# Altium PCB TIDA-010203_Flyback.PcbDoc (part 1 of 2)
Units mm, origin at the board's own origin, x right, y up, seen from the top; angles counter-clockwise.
Board outline 58 x 45 mm, 2 copper layers (Top Layer, Bottom Layer), stack 1.646 mm thick; 65 components, 31 nets, 152 pads, 52 vias.
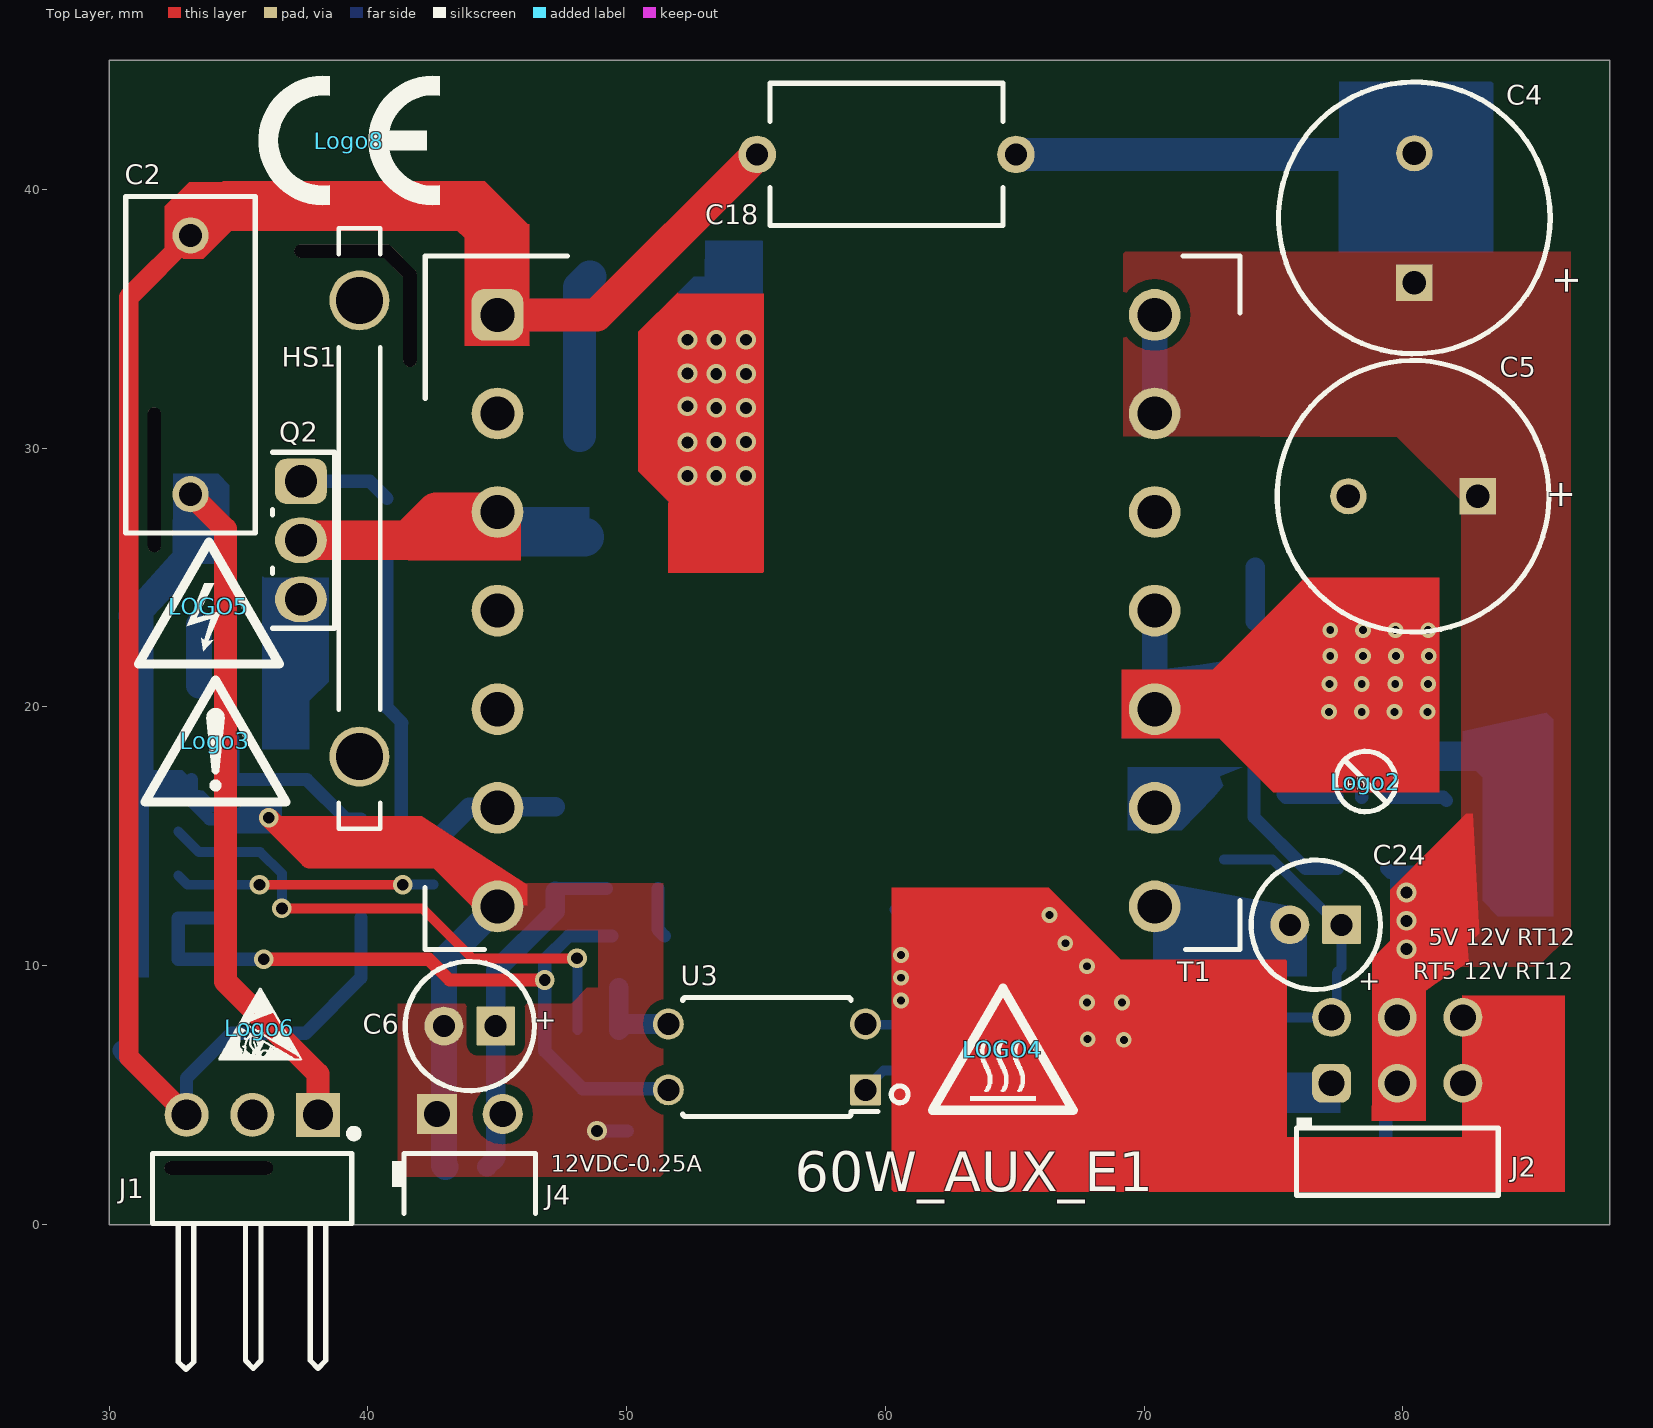
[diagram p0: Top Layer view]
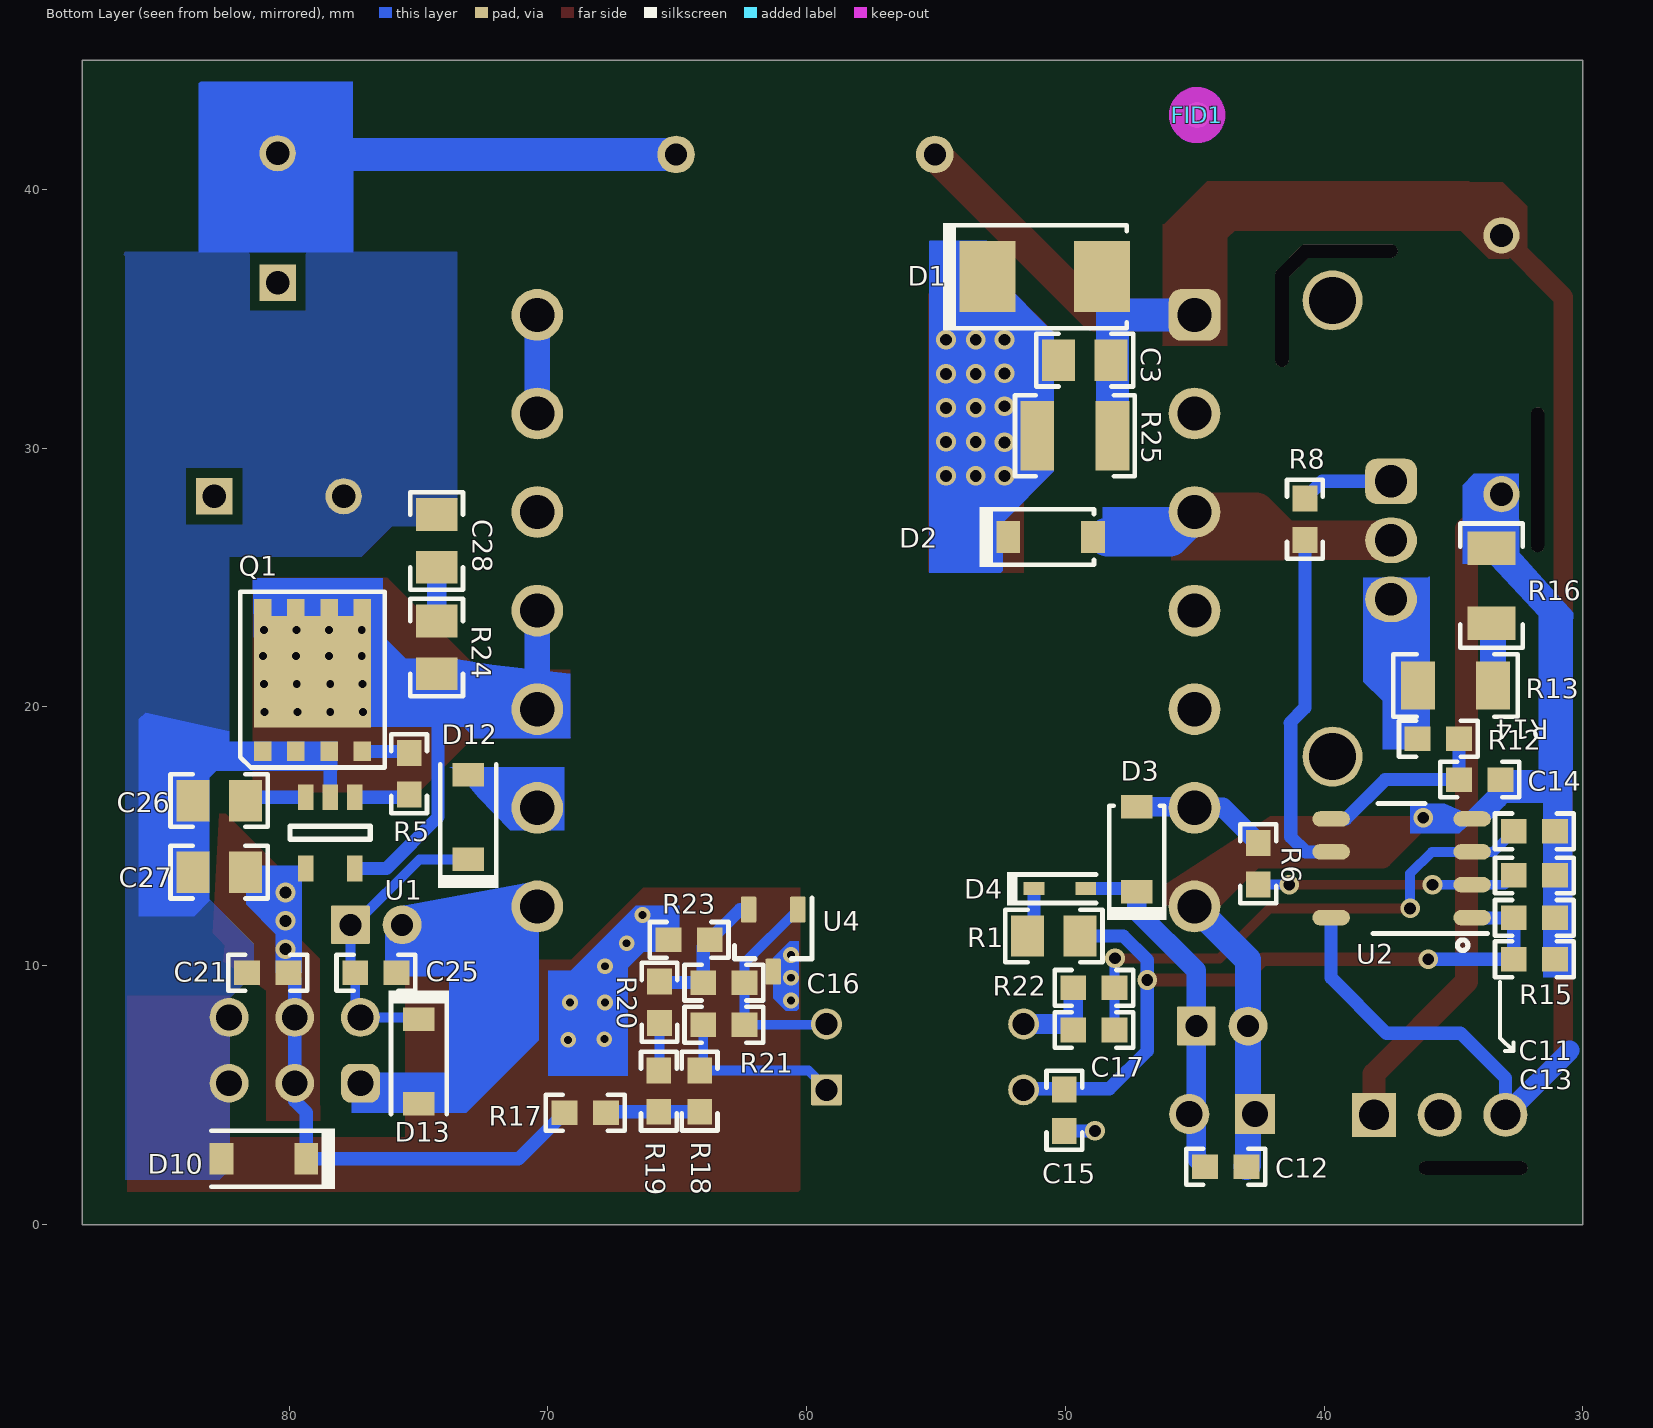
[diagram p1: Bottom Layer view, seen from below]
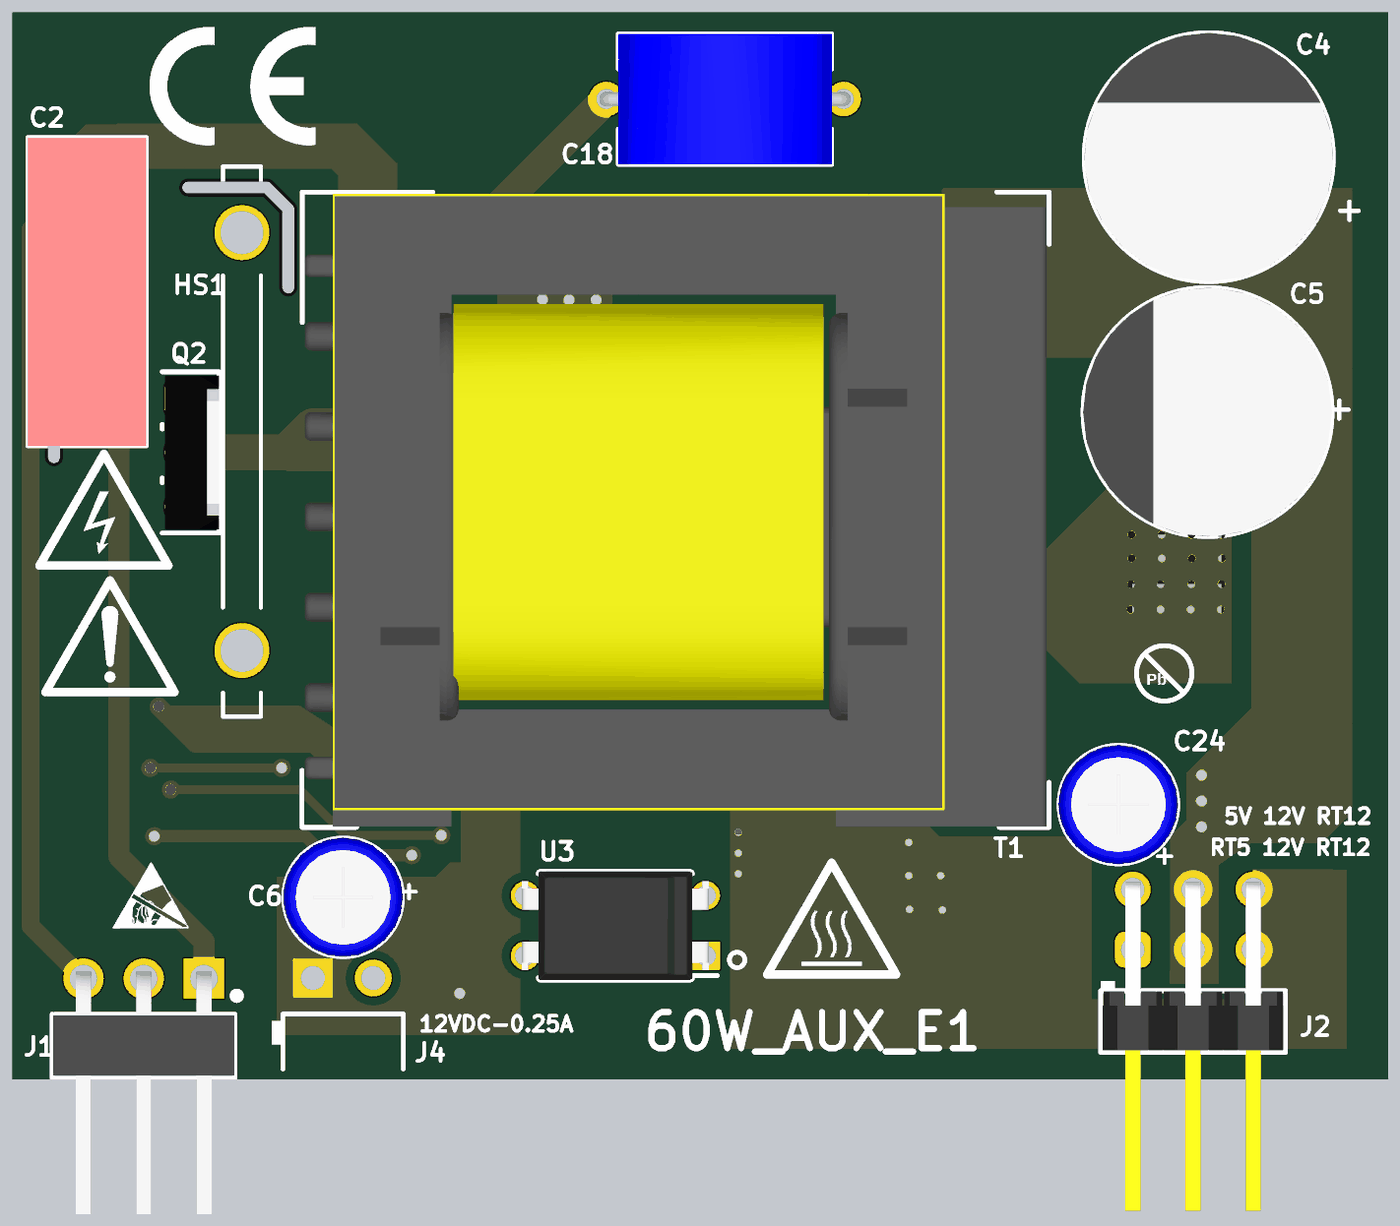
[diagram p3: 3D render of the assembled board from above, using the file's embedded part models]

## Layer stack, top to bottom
Top Solder: solder mask 0.0102, Solder Resist, Dk 3.5
Top Layer: signal copper 0.0711
Dielectric1: core 1.5037, FR-4 High Tg, Dk 4.8
Bottom Layer: signal copper 0.0711
Bottom Solder: solder mask 0.0102, Solder Resist, Dk 3.5

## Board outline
30,0 88,0 88,45 30,45

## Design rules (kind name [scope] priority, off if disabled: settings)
AcuteAngle [All] p1: minimum=4.50000000000000E+0001 checktracksonly=FALSE
AssemblyTestPointUsage [All] p1: valid=2
Clearance Clearance_1 [IsPad vs IsVia] p1: gap=0.203 ignorepadtopadclearanceinfootprint=FALSE except(0: Arc-Hole Track-Hole SMDPad-Hole THPad-Hole Via-Hole Fill-Hole Poly-Hole Region-Hole Text-Hole)
Clearance Clearance_Keepouts [iskeepout vs inpoly] p2: gap=0.508 ignorepadtopadclearanceinfootprint=FALSE except(0: Arc-Hole Track-Hole SMDPad-Hole THPad-Hole Via-Hole Fill-Hole Poly-Hole Region-Hole Text-Hole)
Clearance Clearance_BoardEdge_Poly [OnCopper and InPoly vs IsKeepOut] p3: gap=0.381 ignorepadtopadclearanceinfootprint=FALSE except(0: Arc-Hole Track-Hole SMDPad-Hole THPad-Hole Via-Hole Fill-Hole Poly-Hole Region-Hole Text-Hole)
Clearance Clearance_Poly [InPolygon] p4: gap=0.381 ignorepadtopadclearanceinfootprint=FALSE except(0: Arc-Hole Track-Hole SMDPad-Hole THPad-Hole Via-Hole Fill-Hole Poly-Hole Region-Hole Text-Hole; 0.508: Poly-Poly)
Clearance [All] p5: gap=0.203 ignorepadtopadclearanceinfootprint=FALSE except(0: Arc-Hole Track-Hole SMDPad-Hole THPad-Hole Via-Hole Fill-Hole Poly-Hole Region-Hole Text-Hole)
ComponentClearance [All] p1: gap=0 collisioncheckmode=3 verticalgap=0 showdistances=FALSE
DiffPairsRouting [All] p1: maxlimit=2.54 minlimit=0.254 mostfreqgap=0.254 toplayer_minwidth=0.381 toplayer_maxwidth=0.381 toplayer_prefwidth=0.381 bottomlayer_minwidth=0.381 bottomlayer_maxwidth=0.381 bottomlayer_prefwidth=0.381 maxuncoupledlength=25.4
FabricationTestPointUsage TestPointUsage [All] p1: valid=2 allowmultiple=FALSE
FabricationTestpoint Testpoint [All] p1: side=3 testpointundercomponent=TRUE minsize=1.016 maxsize=2.54 preferedsize=1.524 minholesize=0 maxholesize=1.016 preferedholesize=0.813 testpointgrid=0.025 allowsidetop=TRUE allowsidebottom=TRUE usegrid=TRUE gridtolerance=0
FanoutControl Fanout_LCC [IsLCC] p1: bgadir=Out bgaviamode=Centered fanoutstyle=Auto fanoutdirection=Alternating viagrid=0.025 // Fanout_LCC (Default Rule)
FanoutControl Fanout_BGA [IsBGA] p2: bgadir=Out bgaviamode=Centered fanoutstyle=Auto fanoutdirection=Alternating viagrid=0.025 // Fanout_BGA (Default Rule)
FanoutControl Fanout_Default [All] p4: bgadir=Out bgaviamode=Centered fanoutstyle=Auto fanoutdirection=Alternating viagrid=0.025 // Fanout_Default (Default Rule)
FanoutControl Fanout_Small [(CompPinCount < 5)] p5: bgadir=Out bgaviamode=Centered fanoutstyle=Auto fanoutdirection=OutThenIn viagrid=0.025 // Fanout_Small (Default Rule)
Height [All] p1: minheight=0 maxheight=27 prefheight=12.7
HoleSize [All] p1: absolutevalues=TRUE maxlimit=6.375 minlimit=0.2 maxpercent=80.000 minpercent=20.000
MinimumAnnularRing MinimumAnnularRing_ThermalPadVias [IsVia and InAnyComponent] p1: minimumring=0.15
MinimumAnnularRing [All] p2: minimumring=0.152
MinimumSolderMaskSliver MinimumSolderMaskSliver_Logo [InComponentClass('Logo') vs InComponentClass('Logo')] p1: minsoldermaskwidth=0.018
MinimumSolderMaskSliver [All] p2: minsoldermaskwidth=0.1
PlaneConnect [All] p1: planeconnectstyle=Relief reliefexpansion=0.254 reliefentries=4 reliefconductorwidth=0.254 reliefairgap=0.254
PolygonConnect [All] p1: connectstyle=Direct reliefconductorwidth=0.254 reliefentries=4 polygonreliefangle="90 Angle" airgapwidth=0.254
RoutingVias ThermalPadVias [IsVia and InAnyComponent] p1: holewidth=0.2 width=0.5 viastyle="Through Hole" minholewidth=0.2 minwidth=0.5 maxholewidth=0.33 maxwidth=0.6
RoutingVias [All] p2: holewidth=0.305 width=0.61 viastyle="Through Hole" minholewidth=0.254 minwidth=0.508 maxholewidth=0.457 maxwidth=0.762
SilkToBoardRegionClearance [Not ((IsComment or IsDesignator) And (Hide <> 'False')) and not InRegion(1000,500,4000,800)] p1:
SilkToSilkClearance SilkToSilkClearance_Pb-FreeLogo [(HasFootprint('Pb-Free_Overlay_Medium') OR HasFootprint('Pb-Free_Overlay_Small')) vs (HasFootprint('Pb-Free_Overlay_Medium') OR HasFootprint('Pb-Free_Overlay_Small'))] p1: silktosilkclearance=0
SilkToSilkClearance [All] p2: silktosilkclearance=0.102
SilkToSolderMaskClearance SilkToComonentPadClearance [IsPad and InAnycomponent] p1: minsilkscreentomaskgap=0.127 clearancetoexposedcopper=TRUE
SilkToSolderMaskClearance "Silk to Solder Mask Opening" [All] p2: minsilkscreentomaskgap=0.102 clearancetoexposedcopper=FALSE
SolderMaskExpansion [All] p1: expansion=0.064
Width [All] p1: maxlimit=2.54 minlimit=0.152 preferedwidth=0.254 checkconnectedcopper=TRUE
14 further rules are at their usual default settings.

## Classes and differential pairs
component class TIDA-010203_Flyback: C2 C3 C4 C5 C6 C10 C11 C12 C13 C14 C15 C16 C17 C18 C21 C24 C25 C26 C27 C28 D1 D2 D3 D4 D10 D12 D13 HS1 J1 J2 J4 Logo8 Q1 Q2 R1 R5 R6 R8 R12 R13 R14 R15 R16 R17 R18 R19 R20 R21 R22 R23 R24 R25 T1 U1 U2 U3 U4
component class Header: J2

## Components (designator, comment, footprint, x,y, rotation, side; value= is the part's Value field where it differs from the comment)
C2 "B32671P6104K" WCAP-FTXX_P10PL20_13x5x11 33.147,33.223 r270 top value=0.1uF
C3 "C0805W103KBRAC7800" 0805_HV 49.251,33.401 r0 bottom value=0.01uF
C4 "20SEPF560M" SEPF_F13 80.442,38.898 r90 top value=560uF
C5 "20SEPF560M" SEPF_F13 80.391,28.143 r180 top value=560uF
C6 "25YXJ100M5X11" CAPPR2-5x11 43.942,7.671 r180 top value=100uF
C11 "GRM188R61E105KA12D" 0603 31.875,11.85 r180 bottom value=1uF
C12 "C0603C105K3RACTU" 0603 43.802,2.235 r180 bottom value=1uF
C13 "GRM188R61E106MA73D" 0603 31.875,10.25 r180 bottom value=10uF
C14 "GRM1885C1H330JA01D" 0603 33.985,17.196 r180 bottom value=33pF
C15 "C1608X7R1H104K" 0603 50.038,4.42 r270 bottom value=0.1uF
C16 "C1608C0G1H122J" 0603 63.195,9.347 r180 bottom value=1200pF
C17 "C1608X7R1H473K" 0603 48.895,7.518 r0 bottom value=0.047uF
C18 "DE1E3KX222MN4AP01F" C921_5500T_VertKink 60.046,41.351 r180 top value="2200 pF"
C21 "C0603C105K3RACTU" 0603 80.823,9.728 r0 bottom value=1uF
C24 "25YXJ100M5X11" CAPPR2-5x11 76.632,11.582 r180 top value=100uF
C25 "C0603C105K3RACTU" 0603 76.645,9.728 r180 bottom value=1uF
C26 "GRM219R71C225KE15" 0805_HV 82.702,16.383 r0 bottom value=2.2uF
C27 "GJ821BR71H105KA12L" 0805_HV 82.702,13.614 r0 bottom value=1uF
C28 "08051C331KAT2A" 0805_HV 74.295,26.416 r90 bottom value=330pF
D1 "SMBJ160A" SMB 50.8,36.627 r180 bottom value=160V
D2 "UFM15PL-TP" SOD-123FL 50.571,26.568 r180 bottom value=600V
D3 "PMEG10020AELRX" SOD-123FL 47.244,14.503 r90 bottom value=150V
D4 "1N4148WT" Fairchild_SOD-523F 50.216,12.979 r180 bottom value=75V
D10 "BZT52C15-7-F" SOD-123 80.975,2.54 r0 bottom value=15V
D12 "PMEG6020AELRX" SOD-123 73.076,15.748 r90 bottom value=150V
D13 "MMSZ4691T1G" SOD-123 74.981,6.299 r270 bottom value=6.2V
FID1 "Fiducial" Fiducial10-20 44.907,42.875 r180 bottom
HS1 "ATS-PCBT1093" HS_ATS-PCB1093 39.675,26.899 r270 top
J1 "PEC03SBAN" Sullins_PEC03SBAN 35.535,4.242 r180 top
J2 "90122-0763" Molex_90122-0763 79.781,6.731 r90 top locked
J4 "PEC02SBAN" Sullins_xxC02SBAN 43.942,0.207 r0 top locked
Logo2 "Pb-Free Symbol" Pb-Free_Overlay_Small 78.562,17.12 r0 top
Logo3 "CAUTION.  READ USER GUIDE BEFORE USE" IEC_Caution_Small 34.112,18.694 r0 top
LOGO4 "CAUTION HOT SURFACE" IEC_HotSurface_Small 64.541,6.782 r0 top
LOGO5 "DANGER HIGH VOLTAGE" IEC_HighVoltage_Small 33.858,23.901 r0 top
Logo6 "ESD Susceptible" ESD_Overlay_Small 35.814,7.595 r0 top
Logo8 "CE Mark" CE_Mark_5mm 39.277,41.891 r0 top
Q1 "CSD19531Q5A" TRANS_NexFET_Q5A 79.096,21.06 r90 bottom value=100V
Q2 "IPU80R600P7" IPAK 37.414,26.441 r270 top value=800V
R1 "CRCW080547R5FKEA" 0805_HV 50.444,11.151 r180 bottom value=47.5
R5 "CRCW06031R50FKEA" 0603 75.362,17.424 r90 bottom value=1.50
R6 "CRCW060336K5FKEA" 0603 42.545,13.945 r90 bottom value=36.5k
R8 "CRCW06030000Z0EA" 0603 40.742,27.254 r90 bottom value=0
R12 "CRCW06031K00FKEA" 0603 35.585,18.771 r0 bottom value=1k
R13 "ERJ-8BSFR15V" 1206 34.925,20.828 r0 bottom value=0.15
R14 "16k 0603" 0603 31.874,13.489 r0 bottom value=16k
R15 "CRCW060322K0JNEA" 0603 31.874,15.191 r0 bottom value=22k
R16 "ERJ-8BSFR15V" 1206 33.528,24.689 r270 bottom value=0.15
R17 "CRCW060347R5FKEA" 0603 68.555,4.318 r180 bottom value=47.5
R18 "CRCW06031K50FKEA" 0603 64.135,5.156 r90 bottom value=1.50k
R19 "CRCW060384K5FKEA" 0603 65.71,5.156 r270 bottom value=84.5k
R20 "CRCW060384K5FKEA" 0603 65.684,8.585 r270 bottom value=84.5k
R21 "CRCW06031K00FKEA" 0603 63.195,7.722 r0 bottom value=1.00k
R22 "CRCW0603200KFKEA" 0603 48.895,9.144 r0 bottom value=200k
R23 "CRCW060344K2FKEA" 0603 64.541,10.998 r0 bottom value=44.2k
R24 "MCU08050C4709FP500" 0805_HV 74.295,22.301 r270 bottom value=47.0
R25 "RC1210FR-07511KL" 1210 49.632,30.48 r180 bottom value=511k
T1 "750344721" WE_25/13/7 44.882,12.04 r0 top locked
U1 "UCC24612-1DBVR" DBV0005A_N 78.41,15.138 r270 bottom value=Value
U2 "UCC28740DR" D0007A_N 37.008,13.767 r0 bottom locked
U3 "LTV-817" DIP762W60P254L460H350Q4B 55.423,6.477 r180 top
U4 "ATL431BQDBZR" DBZ0003A_N 61.29,10.973 r270 bottom
ZZ1 "These assemblies are ESD sensitive, ESD precautions shall be observed." AssemblyNote -30.861,72.494 r0 top
ZZ2 "These assemblies must be clean and free from flux and all contaminants. Use of no clean flux is not acceptable." AssemblyNote -30.861,70.245 r0 top
ZZ3 "These assemblies must comply with workmanship standards IPC-A-610 Class 2, unless otherwise specified." AssemblyNote -30.861,67.996 r0 top

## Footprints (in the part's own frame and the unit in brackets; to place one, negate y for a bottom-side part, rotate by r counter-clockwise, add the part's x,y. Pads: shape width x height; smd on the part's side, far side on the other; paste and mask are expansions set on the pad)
0603 [mm] "0603 from SM-752 data"
  rect 1x0.95 smd: 1(-0.8,0) 2(0.8,0)
  silkscreen extent -1.52,-0.69 1.52,0.69, body extent -0.87,-0.47 0.87,0.47, height 1
0805_HV [mil] "0805 with 30mil clearance between pads"
  rect 50x63 smd: 1(-40,0) 2(40,0)
  silkscreen extent -74,-40 74,40, body extent -43,-29 43,29, height 57
1206 [mm] "1206 from SM-752 data"
  rect 1.3x1.85 smd: 1(-1.45,0) 2(1.45,0)
  silkscreen extent -2.4,-1.21 2.4,1.21, body extent -1.7,-0.9 1.7,0.9, height 1.35
1210 [mm] "1210 from SM-752 data"
  rect 1.3x2.7 smd: 1(-1.45,0) 2(1.45,0)
  silkscreen extent -2.32,-1.57 2.32,1.57, body extent -1.7,-1.35 1.7,1.35, height 1.35
AssemblyNote [mm] "Assembly Note"
C921_5500T_VertKink [mm] "Kemet"
  round 1.45 hole 0.85: 1(-5,0) 2(5,0)
  silkscreen extent -4.5,-2.75 4.5,2.75, body extent -5.3,-2.75 5.3,2.75, height 11.99
CAPPR2-5x11 [mm] "Capacitor, Electrolytic, Radial; Body 5 x 11 mm (Dia.xH typ); Pin Spacing 2 mm (typ)"
  rrect7% 1.5x1.5 hole 0.85: 1(-1,0)
  round 1.5 hole 0.85: 2(1,0)
  silkscreen extent -2.5,-2.5 2.5,2.5, body extent -2.53,-2.53 2.53,2.52, height 11.29
CE_Mark_5mm [mm] "Minimum text height for CE Mark"
  silkscreen extent -3.5,-2.5 3.5,2.5
D0007A_N [mm] "SOIC, 7-Leads, Body 4.9x3.9mm, Pitch 1.27mm, IPC Medium Density"
  oval 1.45x0.6 smd: 1(-2.725,1.905) 2(-2.725,0.635) 3(-2.725,-0.635) 4(-2.725,-1.905) 5(2.725,-1.905) 6(2.725,-0.635) 8(2.725,1.905)
  silkscreen extent -3.33,-2.5 1.1,2.53, body extent -3.01,-2.45 3.01,2.45, height 1.75
DBV0005A_N [mm]
  rect 1x0.6 smd paste+0 mask+0: 1(-1.375,0.95) 2(-1.375,0) 3(-1.375,-0.95) 4(1.375,-0.95) 5(1.375,0.95)
  silkscreen extent -0.25,-1.55 0.25,1.55, body extent 0,0 0.25,0.25, height 0.25
DBZ0003A_N [mm] "SOT23, 3-Leads, Body 2.9x1.3mm, Pitch 0.95mm, Lead Span 2.4mm, IPC Medium Density"
  rrect17% 1x0.6 smd: 1(-1.2,0.95) 2(-1.2,-0.95) 3(1.2,0)
  silkscreen extent -1.65,-1.5 0.7,1.5, body extent -1.26,-1.46 1.26,1.46, height 0.98
DIP762W60P254L460H350Q4B [mm] "LITE-ON"
  rrect8% 1.2x1.2 hole 0.85: 1(-3.81,1.27)
  round 1.2 hole 0.85: 2(-3.81,-1.27) 3(3.81,-1.27) 4(3.81,1.27)
  silkscreen extent -5.46,-2.29 3.25,2.3, body extent -3.94,-2.29 3.94,2.3, height 4.3
ESD_Overlay_Small [mm]
  silkscreen extent -1.58,-1.23 1.62,1.55
Fairchild_SOD-523F [mm] "SMD, 2-Leads, Body 1.2x0.8mm"
  rect 0.8x0.5 smd: 1(-1,0) 2(1,0)
  silkscreen extent -2.03,-0.65 1.4,0.65, body extent -0.65,-0.45 0.65,0.45, height 0.7
Fiducial10-20 [mm]
  round 1 smd mask+0.5: 1(0,0)
  Top Layer keep-out circle w1.178: c0,0 r0.5
HS_ATS-PCB1093 [mm] "HEATSINK, TH-2P"
  round 2.314 hole 1.814: 1(-8.815,0) 2(8.815,0)
  silkscreen extent -11.6,-0.8 11.6,0.8, body extent -11.6,-0.8 11.6,0.8, height 31.8
IEC_Caution_Small [mm]
  silkscreen extent -2.72,-2.36 2.72,2.35
IEC_HighVoltage_Small [mm]
  silkscreen extent -2.72,-2.24 2.72,2.47
IEC_HotSurface_Small [mm]
  silkscreen extent -2.72,-2.36 2.72,2.35
IPAK [mm] "IPAK"
  rrect50% 1.75x2 hole 1.25: 1(-2.28,0)
  oval 1.75x2 hole 1.25: 2(0,0) 3(2.28,0)
  silkscreen extent -3.4,-1.1 3.4,1.3, body extent -3.25,-0.99 3.25,1.31, height 9.66
Molex_90122-0763 [mm] "Header, 2.54mm, 3x2, R/A, TH"
  rrect50% 1.5x1.5 hole 1: 1(-1.27,2.54)
  round 1.5 hole 1: 2(1.27,2.54) 3(-1.27,0) 4(1.27,0) 5(-1.27,-2.54) 6(1.27,-2.54)
  silkscreen extent -5.6,-3.9 -2.6,3.9, body extent -12.27,-3.81 1.57,3.81, height 6.35
Pb-Free_Overlay_Small [mm]
  silkscreen extent -1.16,-1.17 1.17,1.17
SEPF_F13 [mm] "TH, 2-Leads, Dia 10mm, Pin Spacing 5mm"
  rect 1.4x1.4 hole 0.9: 1(-2.5,0)
  round 1.4 hole 0.9: 2(2.5,0)
  silkscreen extent -5.25,-5.25 5.25,5.25, body extent -5.25,-5.24 5.25,5.24, height 13.01
SMB [mm] "Molded Diode, 2-Leads, Body 5.4x3.6mm, IPC Medium Density, based on OnSemi component dimensions"
  rect 2.159x2.743 smd: 1(-2.21,0) 2(2.21,0)
  silkscreen extent -3.94,-2.08 3.18,2.08, body extent -2.7,-1.8 2.7,1.8, height 2.32
SOD-123 [mm] "On Semi recommended land pattern"
  rect 0.915x1.22 smd: 1(-1.637,0) 2(1.637,0)
  silkscreen extent -2.74,-1.17 2.03,1.17, body extent -1.93,-0.9 1.93,0.9, height 1.35
SOD-123FL [mm] "Copied from SOD-123"
  rect 0.915x1.22 smd: 1(-1.637,0) 2(1.637,0)
  silkscreen extent -2.74,-1.16 1.68,1.16, body extent -1.9,-0.9 1.9,0.9, height 1
Sullins_PEC03SBAN [mm] "Sullins"
  rect 1.7x1.7 hole 1.16: 1(-2.54,0)
  round 1.7 hole 1.16: 2(0,0) 3(2.54,0)
  silkscreen extent -4.07,0.58 3.86,9.85, body extent -3.81,-0.29 3.81,9.94, height 3.56
Sullins_xxC02SBAN [mm] "Header, 2.54 mm, 2x1, R/A, TH"
  rect 1.55x1.55 hole 1.016: 1(-1.27,4.06)
  round 1.55 hole 1.016: 2(1.27,4.06)
  silkscreen extent -3,0.22 2.54,2.54, body extent -2.54,-5.84 2.54,4.38, height 3.56
TRANS_NexFET_Q5A [mm] "TI recommended land pattern (nominal) M0139-01"
  rect 0.75x0.675 smd paste-0.1 mask+0.051: 1(-2.776,1.917) 2(-2.776,0.639) 3(-2.776,-0.639) 4(-2.776,-1.917)
  rect 0.655x0.675 smd paste-0.1 mask+0.051: 5(2.776,-1.917) 6(2.776,-0.639) 7(2.776,0.639) 8(2.776,1.917)
  rect 4.295x4.51 smd paste-2.2 mask+0.051: 9(0.301,0)
  silkscreen extent -3.4,-2.8 3.4,2.8, body extent -3.05,-2.5 3.05,2.5, height 1.11
WCAP-FTXX_P10PL20_13x5x11 [mm] "TH, 2-Leads, Body 13x5mm, Pitch 10mm"
  round 1.4 hole 0.9: 1(-5,0) 2(5,0)
  silkscreen extent -6.5,-2.5 6.5,2.5, body extent -6.5,-2.5 6.5,2.5, height 11
WE_25/13/7 [mm]
  rrect50% 2x2 hole 1.32: 1(0.127,23.114)
  round 2 hole 1.32: 2(0.127,19.304) 3(0.127,15.494) 4(0.127,11.684) 5(0.127,7.874) 6(0.127,4.064) 7(0.127,0.254) 8(25.527,0.254) 9(25.527,4.064) 10(25.527,7.874) 11(25.527,11.684) 12(25.527,15.494) 13(25.527,19.304) 14(25.527,23.114)
  silkscreen extent -2.67,-1.42 28.83,25.38, body extent -2.56,-1.38 28.73,25.31, height 22.86

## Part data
C2: library part 890334023006, "CAP, Film, 0.1 μF, 630 V, +/- 10%, TH", Cap_Case=13x5x11mm, Manufacturer=TDK, Supplier Part Number 1=495-4746-ND, Tolerance_%=10, Value1=Unknown, Value2=630V, ValueDisplayed=0.1μF
C3: library part C0805C103K1RACTU, "10000pF 630V Ceramic Capacitor X7R 0805", Cap_Case=0805, Manufacturer=Kemet, Supplier Part Number 1=399-12313-6-ND, TempCo=X7R, Tolerance_%=10, Value1="1.739 ohm", Value2=630V, ValueDisplayed=10nF
C4 C5: library part CMP-0081667-1, "CAP, Aluminum Polymer, 560 μF, 20 V,+/- 20%, 0.012 ohm, TH", Cap_Case=10x13mm, Manufacturer=Panasonic, Supplier Part Number 1=P16316-ND, Tolerance_%=20%, Value1="0.012 ohm", Value2=20V, ValueDisplayed=560μF
C6 C24: library part UVR1V100MDD1TA, "CAP, AL, 100 μF, 25 V, +/- 20%, TH", Cap_Case=5x11, Manufacturer=Rubycon, Supplier Part Number 1=1189-2237-ND, Tolerance_%=20, Value1=Unknown, Value2=25V, ValueDisplayed=100μF
C11: "CAP, CERM, 1 μF, 25 V, +/- 10%, X5R, 0603", Cap_Case=0603, Manufacturer=MuRata, Supplier Part Number 1=490-3897-1-ND, TempCo=X5R, Tolerance_%=10, Value1=Unknown, Value2=25V, ValueDisplayed=1μF
C12 C21 C25: library part C0603C105K8PACTU, "CAP CER 1UF 25V X7R 0603", Cap_Case=0603, Manufacturer=Kemet, Supplier Part Number 1=399-7376-1-ND, TempCo=X5R, Tolerance_%=10, Value1=Unknown, Value2=10V, ValueDisplayed=1μF
C13: "CAP, CERM, 10 μF, 25 V, +/- 20%, X5R, 0603", Cap_Case=0603, Manufacturer=MuRata, Supplier Part Number 1=490-7202-1-ND, TempCo=X5R, Tolerance_%=20, Value1=Unknown, Value2=25V, ValueDisplayed=10μF
C14: "CAP, CERM, 33 pF, 50 V, +/- 5%, C0G/NP0, 0603", Cap_Case=0603, Manufacturer=MuRata, Supplier Part Number 1=490-1415-1-ND, TempCo=C0G/NP0, Tolerance_%=5, Value1=Unknown, Value2=50V, ValueDisplayed=33pF
C15: "CAP, CERM, 0.1 μF, 50 V, +/- 10%, X7R, 0603", Cap_Case=0603, Manufacturer=TDK, Supplier Part Number 1=445-1314-1-ND, TempCo=X7R, Tolerance_%=10, Value1="0.017 ohm", Value2=50V, ValueDisplayed=0.1μF
C16: "CAP, CERM, 1200 pF, 50 V, +/- 5%, C0G/NP0, 0603", Cap_Case=0603, Manufacturer=TDK, Supplier Part Number 1=445-1294-1-ND, TempCo=C0G/NP0, Tolerance_%=5, Value1=Unknown, Value2=50V, ValueDisplayed=1200pF
C17: "CAP, CERM, 0.047 μF, 50 V, +/- 10%, X7R, 0603", Cap_Case=0603, Manufacturer=TDK, Supplier Part Number 1=445-1313-1-ND, TempCo=X7R, Tolerance_%=10, Value1="0.0234 ohm", Value2=50V, ValueDisplayed=0.047μF
C18: library part C921U222MUVDBA7317, "CAP, CERM, 2.2 μF, 250 V, +/- 20%, Y5V, Cap 9x13mm", Cap_Case=C921_5500T_VertKink, Manufacturer=Kemet, Supplier Part Number 1=490-9514-3-ND, TempCo=Y5V, Tolerance_%=20, Value1=Unknown, Value2="300 V", ValueDisplayed="2200 pF"
C26: library part CMP-0008211-2, "CAP, CERM, 2.2 uF, 16 V, +/- 10%, X7R, 0805", Cap_Case=0805, Manufacturer=MuRata, TempCo=X7R, Tolerance_%=10%, Value1=Unknown, Value2=16V, ValueDisplayed=2.2uF
C27: library part CMP-0750127-1, "CAP, CERM, 1 μF, 50 V,+/- 10%, X7R, 0805", Cap_Case=0805, Manufacturer=MuRata, TempCo=X7R, Tolerance_%=10%, Value2=50V, ValueDisplayed=1μF
C28: library part CMP-0007553-2, "CAP, CERM, 330 pF, 100 V, +/- 10%, X7R, 0805", Cap_Case=0805, Manufacturer=AVX, Supplier Part Number 1=478-1349-1-ND, TempCo=X7R, Tolerance_%=10%, Value1="0.563 ohm", Value2=100V, ValueDisplayed=330pF
D1: library part SMBJ160A-13-F, "TVS DIODE 160VWM 259VC SMB", Manufacturer="Fairchild Semiconductor", Power_W=5, Supplier Part Number 1=SMBJ160AFSCT-ND, Value1=5W
D2: library part CMP-0029148-2, "Diode, Ultrafast, 600 V, 1 A, SOD-123FL", Manufacturer="Micro Commercial Components", Value1=1A, Value2=1.7V
D3: library part MBR1H100SFT3G, "DIODE SCHOTTKY 100V 2A SOD2123", Manufacturer="NXP Semiconductors", Supplier Part Number 1=568-12569-1-ND, Value1=1A, Value2=0.85V
D4: "Diode, Switching, 75 V, 0.3 A, SOD-523F", Manufacturer="Fairchild Semiconductor", Supplier Part Number 1=1N4148WTCT-ND, Value1=0.3A, Value2=V
D10: "Diode, Zener, 15 V, 370 mW, AEC-Q101, SOD-123", Manufacturer="Diodes Inc.", Power_W=0.37, Supplier Part Number 1=BZT52C15-FDICT-ND, Value1=0.37W
D12: library part MBR1H100SFT3G, "DIODE SCHOTTKY 60V 2A SOD2123", Manufacturer="NXP Semiconductors", Supplier Part Number 1=568-12569-1-ND, Value1=1A, Value2=0.85V
D13: library part BZT52C15-7-F, "Diode, Zener, 15 V, 370 mW, AEC-Q101, SOD-123", Manufacturer="Diodes Inc.", Power_W=0.37, Supplier Part Number 1=BZT52C15-FDICT-ND, Value1=0.37W
FID1: library part CMP-0077181-1, "Fiducial mark.  There is nothing to buy or mount.", Manufacturer=N/A
HS1: library part 150CN-02000-A-200, "Heat Sink TO-220 Copper Board Level, Vertical", Manufacturer="Advanced Thermal Solutions Inc.", Supplier Part Number 1=ATS2135-ND
J1: library part CMP-0054704-1, "Header, 100mil, 3x1, Tin, R/A, TH", Color=Black, Current_A=3A, Manufacturer="Sullins Connector Solutions", Supplier Part Number 1=S1112E-03-ND, Voltage_V=1.8kV
J2: library part CMP-0077741-2, "Header, 2.54mm, 3x2, Gold, R/A, TH", Color=Black, Current_A=3A, Manufacturer=Molex, Supplier Part Number 1=WM50030-06-ND, Voltage_V=350V
J4: "Header, 2.54 mm, 2x1, Tin, R/A, TH", Color=Black, Current_A=3, Manufacturer="Sullins Connector Solutions", Supplier Part Number 1=S1112E-02-ND, Voltage_V=1800
Logo2: library part Pb-Free
Logo3: library part CMP-0074847-1, "FCC_disclaimer"
LOGO4: library part IEC_HotSurface, "IEC 61010-1 Hot Surface Warning"
LOGO5: library part IEC_HighVoltage, "IEC 61010-1 High Voltage Warning"
Logo6: library part ESD_Susceptible, "ESD Susceptible Symbol"
Logo8: library part CMP-0074844-1
Q1: "MOSFET, N-CH, 100 V, 16 A, SON 5x6mm", Alternate Manufacturer=None, Manufacturer="Texas Instruments", Supplier Part Number 1=CSD19531Q5A-ND, Value1="? ohm", Value2="36 nC"
Q2: library part IPU60R2K0C6BKMA1, "MOSFET, N-CH, 650 V, 2.4 A, IPAK", Alternate Manufacturer=None, Manufacturer="Infineon Technologies", Supplier Part Number 1=IPU80R1K0CEBKMA1-ND, Value1="? ohm", Value2="6.7 nC"
R1: "RES, 47.5, 1%, 0.125 W, 0805", Manufacturer=Vishay-Dale, Power_W=0.125, Supplier Part Number 1=541-47.5CCT-ND, TempCo="100 ppm/C", Tolerance_%=1, Value1=1%, Value2=0.125W, Value_Code=47R5, ValueDisplayed=47.5
R5: "RES, 1.50, 1%, 0.1 W, 0603", Manufacturer=Vishay-Dale, Power_W=0.1, Supplier Part Number 1=541-1.50HHCT-ND, TempCo="100 ppm/C", Tolerance_%=1, Value1=1%, Value2=0.1W, Value_Code=1R50, ValueDisplayed=1.50
R6: library part CRCW060346K4FKEA, "RES, 36.5 k, 1%, 0.1 W, 0603", Manufacturer=Vishay-Dale, Power_W=0.1, Supplier Part Number 1=541-46.4KHCT-ND, TempCo="100 ppm/C", Tolerance_%=1, Value1=1%, Value2=0.1W, Value_Code=36.5k
R8: "RES, 0, 5%, 0.1 W, 0603", Manufacturer=Vishay-Dale, Power_W=0.1, Supplier Part Number 1=541-0.0GCT-ND, TempCo="200 ppm/C", Tolerance_%=5, Value1=5%, Value2=0.1W, Value_Code=0000, ValueDisplayed=0
R12: library part CRCW06031K87FKEA, "RES, 1.00k, 1%, 0.1 W, 0603", Manufacturer=Vishay-Dale, Power_W=0.1, TempCo="100 ppm/C", Tolerance_%=1, Value1=1%, Value2=0.1W, Value_Code=1k, ValueDisplayed=1.00k
R13 R16: library part CMP-0017277-2, "RES, 0.15, 1%, 0.5 W, 1206", Manufacturer=Panasonic, Power_W=500mW, Supplier Part Number 1=P16006CT-ND, TempCo="250 ppm/C", Tolerance_%=1%, Value2=0.5W, Value_Code=R150, ValueDisplayed=0.15
R14: library part CMP-0025723-4, "RES, 16 k, 5%, 0.1 W, AEC-Q200 Grade 0, 0603", Manufacturer=Vishay-Dale, PartNumber=CRCW060316K0JNEA, Power_W=100mW, Supplier Part Number 1=541-16KGCT-ND, TempCo="200 ppm/C", Tolerance_%=5%, Value2=0.1W, Value_Code=16k
R15: "RES, 22 k, 5%, 0.1 W, 0603", Manufacturer=Vishay-Dale, Power_W=0.1, Supplier Part Number 1=541-22KGCT-ND, TempCo="200 ppm/C", Tolerance_%=5, Value1=5%, Value2=0.1W, Value_Code=22k0, ValueDisplayed=22k
R17: "RES, 47.5, 1%, 0.1 W, 0603", Manufacturer=Vishay-Dale, Power_W=0.1, Supplier Part Number 1=541-47.5HCT-ND, TempCo="100 ppm/C", Tolerance_%=1, Value1=1%, Value2=0.1W, Value_Code=47R5, ValueDisplayed=47.5
R18: "RES, 1.50 k, 1%, 0.1 W, 0603", Manufacturer=Vishay-Dale, Power_W=0.1, Supplier Part Number 1=541-1.50KHCT-ND, TempCo="100 ppm/C", Tolerance_%=1, Value1=1%, Value2=0.1W, Value_Code=1k50, ValueDisplayed=1.50k
R19 R20: "RES, 84.5 k, 1%, 0.1 W, 0603", Manufacturer=Vishay-Dale, Power_W=0.1, Supplier Part Number 1=541-84.5KHCT-ND, TempCo="100 ppm/C", Tolerance_%=1, Value1=1%, Value2=0.1W, Value_Code=84k5, ValueDisplayed=84.5k
R21: "RES, 1.00 k, 1%, 0.1 W, 0603", Manufacturer=Vishay-Dale, Power_W=0.1, Supplier Part Number 1=541-1.00KHCT-ND, TempCo="100 ppm/C", Tolerance_%=1, Value1=1%, Value2=0.1W, Value_Code=1k00, ValueDisplayed=1.00k
R22: "RES, 200 k, 1%, 0.1 W, 0603", Manufacturer=Vishay-Dale, Power_W=0.1, Supplier Part Number 1=541-200KHCT-ND, TempCo="100 ppm/C", Tolerance_%=1, Value1=1%, Value2=0.1W, Value_Code=200k
R23: "RES, 44.2 k, 1%, 0.1 W, 0603", Manufacturer=Vishay-Dale, Power_W=0.1, Supplier Part Number 1=541-44.2KHCT-ND, TempCo="100 ppm/C", Tolerance_%=1, Value1=1%, Value2=0.1W, Value_Code=44k2, ValueDisplayed=44.2k
R24: library part CMP-0021861-2, "RES, 47.0, 1%, 0.2 W, 0805", Manufacturer=Vishay/Beyschlag, Power_W=200mW, Supplier Part Number 1=MCU08050C4709FP500-ND, TempCo="50 ppm/C", Tolerance_%=1%, Value2=0.2W, Value_Code=47R0, ValueDisplayed=47.0
R25: library part CMP-0083237-1, "RES, 511 k, 1%, 0.5 W, 1210", Manufacturer=Yageo, Power_W=500mW, TempCo="100 ppm/C", Tolerance_%=1%, Value2=0.5W, Value_Code=511k
T1: library part WE_trans, "flyback transformer"
U1: "Imported", Manufacturer="Texas Instruments"
U2: "Constant-Voltage, Constant-Current Flyback Controller Using Opto-Coupler Feedback, D0007A", Alternate Manufacturer="Texas Instruments", Alternate PartNumber=UCC28740D, Supplier Part Number 1=296-41059-1-ND
U3: "Optocoupler, 5 kV, 50-600% CTR, TH-4", Manufacturer=Lite-On, Supplier Part Number 1=160-1366-5-ND, Voltage_Isolation_Vrms=5000
U4: "2.5V Low Iq Adjustable Precision Shunt Regulator, DBZ0003A", Alternate Manufacturer="Texas Instruments", Alternate PartNumber=ATL431BQDBZT
ZZ1: library part CMP-0003616-3, "This Assembly Note is for PCB labels only", Alternate Manufacturer=-
ZZ2: library part CMP-0077236-1, "These assemblies are ESD sensitive, ESD precautions shall be observed.", Alternate Manufacturer=-
ZZ3: library part CMP-0077237-1, "These assemblies must be clean and free from flux and all contaminants. Use of no clean flux is not acceptable.", Alternate Manufacturer=-

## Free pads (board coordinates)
  oval 0.508x5.588 hole 0.508 slot 5.588 at 90 deg unplated mask+0.127: 0(31.75,28.778)
  oval 4.191x0.508 hole 0.508 slot 4.191 at 0 deg unplated mask+0.127: 0(34.239,2.184)
  oval 3.81x0.508 hole 0.508 slot 3.81 at 0 deg unplated mask+0.127: 0(39.065,37.617)
  oval 0.508x1.778 hole 0.508 slot 1.778 at 135 deg unplated rot 45 mask+0.127: 0(41.173,37.16)
  oval 0.508x3.81 hole 0.508 slot 3.81 at 90 deg unplated mask+0.127: 0(41.631,35.052)

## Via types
v1: diameter 0.762, hole 0.457, Top Layer to Bottom Layer, tented both sides, 26 vias
v2: diameter 0.61, hole 0.305, Top Layer to Bottom Layer, tented both sides, 26 vias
